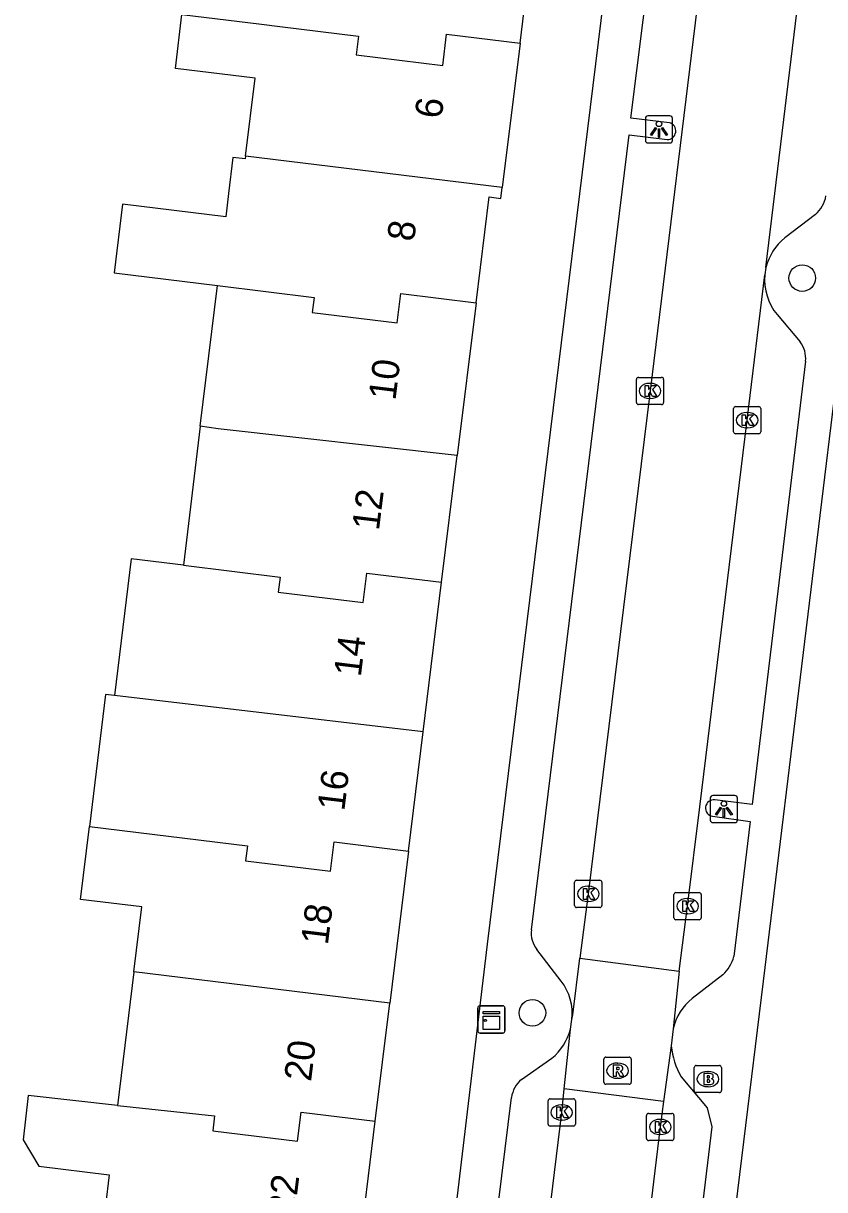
# Model space of a CAD drawing. Extents: x 158087 to 159494, y 382905 to 383981.
# Drawn here: x 158294.96 to 158324.41, y 383327.57 to 383370.44 of the extents above; entities that cross this region are included whole.
import ezdxf

# ---------------------------------------------------------------- set-up
doc = ezdxf.new("R2010")
doc.units = 0
for name, color, linetype in [('IMGEO_Boom', 7, 'Continuous'), ('IMGEO_Brandkraan', 7, 'Continuous'), ('IMGEO_Kast', 7, 'Continuous'), ('IMGEO_Kolk', 7, 'Continuous'), ('IMGEO_Lichtpunt', 7, 'Continuous'), ('IMGEO_Pand', 7, 'Continuous'), ('IMGEO_Pand_nummerreeks', 7, 'Continuous'), ('IMGEO_Rijbaan_lokaal_open', 7, 'Continuous'), ('IMGEO_Rioolput', 7, 'Continuous'), ('IMGEO_Voetpad_open', 7, 'Continuous')]:
    doc.layers.add(name, color=color, linetype=linetype)

msp = doc.modelspace()

# ---------------------------------------------------------------- linework, layer by layer
at = {"layer": 'IMGEO_Boom'}
for centre in [(158323.591, 383361.078), (158313.671, 383334.068)]:
    msp.add_circle(centre, 0.489, dxfattribs=at)
at = {"layer": 'IMGEO_Brandkraan'}
for p, q in [((158319.621, 383331.209), (158319.621, 383332.061)), ((158319.696, 383332.135), (158320.548, 383332.135)), ((158320.109, 383331.915), (158320.134, 383331.915)), ((158320.622, 383332.061), (158320.622, 383331.209)), ((158320.132, 383331.355), (158320.107, 383331.355)), ((158320.548, 383331.135), (158319.696, 383331.135))]:
    msp.add_line(p, q, dxfattribs=at)
for points in [[(158319.621, 383331.209), (158319.621, 383332.061)], [(158319.696, 383332.135), (158320.548, 383332.135)], [(158319.969, 383331.835), (158319.969, 383331.435), (158320.182, 383331.435)], [(158320.2, 383331.835), (158319.969, 383331.835)], [(158320.622, 383332.061), (158320.622, 383331.209)], [(158320.148, 383331.754), (158320.094, 383331.754), (158320.094, 383331.678)], [(158320.094, 383331.678), (158320.147, 383331.678)], [(158320.156, 383331.602), (158320.094, 383331.602), (158320.094, 383331.521)], [(158320.094, 383331.521), (158320.156, 383331.521)], [(158320.548, 383331.135), (158319.696, 383331.135)]]:
    msp.add_lwpolyline(points, dxfattribs=at)
for centre, radius, start, end in [((158319.698, 383332.059), 0.0765, 91.552, 178.448), ((158319.698, 383332.059), 0.0765, 91.552, 178.448), ((158320.204, 383331.69), 0.145, 59.4692, 91.5367), ((158320.229, 383331.737), 0.0922, 285.5137, 58.1501), ((158320.546, 383332.059), 0.0765, 1.552, 88.448), ((158320.546, 383332.059), 0.0765, 1.552, 88.448), ((158320.149, 383331.716), 0.0379, 267.8285, 90.9355), ((158320.157, 383331.561), 0.0404, 269.8759, 90.5077), ((158320.188, 383331.686), 0.251, 268.6676, 293.5347), ((158320.234, 383331.545), 0.105, 301.3115, 78.989), ((158319.698, 383331.211), 0.0765, 181.552, 268.448), ((158319.698, 383331.211), 0.0765, 181.552, 268.448), ((158320.546, 383331.211), 0.0765, 271.552, 358.448), ((158320.546, 383331.211), 0.0765, 271.552, 358.448)]:
    msp.add_arc(centre, radius, start, end, dxfattribs=at)
for centre, major_axis, ratio, start_param, end_param in [((158320.108, 383331.635), (-0.387, 0.002), 0.722429, 4.712389, 7.853982), ((158320.133, 383331.635), (-0.39, 0.002), 0.717154, 1.570796, 4.712389)]:
    msp.add_ellipse(centre, major_axis=major_axis, ratio=ratio, start_param=start_param, end_param=end_param, dxfattribs=at)
at = {"layer": 'IMGEO_Kast'}
for p, q in [((158311.663, 383333.403), (158311.663, 383334.244)), ((158311.663, 383334.244), (158311.663, 383333.403)), ((158311.738, 383334.328), (158312.579, 383334.328)), ((158312.579, 383334.328), (158311.738, 383334.328)), ((158312.663, 383334.253), (158312.663, 383333.412)), ((158312.663, 383333.412), (158312.663, 383334.253)), ((158312.588, 383333.328), (158311.747, 383333.328)), ((158311.747, 383333.328), (158312.588, 383333.328))]:
    msp.add_line(p, q, dxfattribs=at)
for points in [[(158311.858, 383334.118), (158312.458, 383334.118), (158312.458, 383334.033), (158311.858, 383334.033), (158311.858, 383334.118)], [(158311.858, 383333.943), (158312.458, 383333.943), (158312.458, 383333.454), (158311.858, 383333.454), (158311.858, 383333.943)]]:
    msp.add_lwpolyline(points, dxfattribs=at)
msp.add_circle((158311.942, 383333.792), 0.0377, dxfattribs=at)
for centre, start, end in [((158311.741, 383334.25), 92.4484, 184.2845), ((158311.741, 383334.25), 92.4484, 184.2845), ((158312.585, 383334.25), 2.4484, 94.2845), ((158312.585, 383334.25), 2.4484, 94.2845), ((158311.741, 383333.406), 182.4484, 274.2845), ((158311.741, 383333.406), 182.4484, 274.2845), ((158312.585, 383333.406), 272.4484, 4.2845), ((158312.585, 383333.406), 272.4484, 4.2845)]:
    msp.add_arc(centre, 0.0779, start, end, dxfattribs=at)
at = {"layer": 'IMGEO_Kolk'}
for p, q in [((158317.495, 383356.503), (158317.495, 383357.355)), ((158317.57, 383357.429), (158318.422, 383357.429)), ((158317.983, 383357.209), (158318.008, 383357.209)), ((158318.496, 383357.355), (158318.496, 383356.503)), ((158318.006, 383356.649), (158317.981, 383356.649)), ((158318.422, 383356.429), (158317.57, 383356.429)), ((158321.065, 383355.429), (158321.065, 383356.281)), ((158321.14, 383356.355), (158321.992, 383356.355)), ((158322.066, 383356.281), (158322.066, 383355.429)), ((158321.553, 383356.135), (158321.578, 383356.135)), ((158321.576, 383355.575), (158321.551, 383355.575)), ((158321.992, 383355.355), (158321.14, 383355.355)), ((158315.224, 383338.015), (158315.224, 383338.867)), ((158315.299, 383338.941), (158316.151, 383338.941)), ((158315.712, 383338.721), (158315.737, 383338.721)), ((158316.225, 383338.867), (158316.225, 383338.015)), ((158318.875, 383337.564), (158318.875, 383338.416)), ((158318.95, 383338.49), (158319.802, 383338.49)), ((158319.363, 383338.27), (158319.388, 383338.27)), ((158319.876, 383338.416), (158319.876, 383337.564)), ((158316.151, 383337.941), (158315.299, 383337.941)), ((158315.735, 383338.161), (158315.71, 383338.161)), ((158319.802, 383337.49), (158318.95, 383337.49)), ((158319.386, 383337.71), (158319.361, 383337.71)), ((158314.25, 383329.982), (158314.25, 383330.834)), ((158314.325, 383330.908), (158315.177, 383330.908)), ((158314.738, 383330.688), (158314.763, 383330.688)), ((158315.251, 383330.834), (158315.251, 383329.982)), ((158314.761, 383330.128), (158314.736, 383330.128)), ((158317.871, 383329.448), (158317.871, 383330.3)), ((158317.946, 383330.374), (158318.798, 383330.374)), ((158318.359, 383330.154), (158318.384, 383330.154)), ((158318.872, 383330.3), (158318.872, 383329.448)), ((158315.177, 383329.908), (158314.325, 383329.908)), ((158318.798, 383329.374), (158317.946, 383329.374)), ((158318.382, 383329.594), (158318.357, 383329.594))]:
    msp.add_line(p, q, dxfattribs=at)
for points in [[(158317.495, 383356.503), (158317.495, 383357.355)], [(158317.57, 383357.429), (158318.422, 383357.429)], [(158317.816, 383357.129), (158317.939, 383357.129), (158317.939, 383356.978), (158318.069, 383357.129), (158318.233, 383357.129), (158318.087, 383356.978), (158318.24, 383356.729), (158318.088, 383356.729), (158318.003, 383356.893), (158317.939, 383356.826), (158317.939, 383356.729), (158317.816, 383356.729), (158317.816, 383357.129)], [(158318.496, 383357.355), (158318.496, 383356.503)], [(158318.422, 383356.429), (158317.57, 383356.429)], [(158321.065, 383355.429), (158321.065, 383356.281)], [(158321.14, 383356.355), (158321.992, 383356.355)], [(158322.066, 383356.281), (158322.066, 383355.429)], [(158321.386, 383356.055), (158321.509, 383356.055), (158321.509, 383355.904), (158321.639, 383356.055), (158321.803, 383356.055), (158321.657, 383355.904), (158321.81, 383355.655), (158321.658, 383355.655), (158321.573, 383355.819), (158321.509, 383355.752), (158321.509, 383355.655), (158321.386, 383355.655), (158321.386, 383356.055)], [(158321.992, 383355.355), (158321.14, 383355.355)], [(158315.224, 383338.015), (158315.224, 383338.867)], [(158315.299, 383338.941), (158316.151, 383338.941)], [(158315.545, 383338.641), (158315.668, 383338.641), (158315.668, 383338.49), (158315.798, 383338.641), (158315.962, 383338.641), (158315.816, 383338.49), (158315.969, 383338.241), (158315.817, 383338.241), (158315.732, 383338.405), (158315.668, 383338.338), (158315.668, 383338.241), (158315.545, 383338.241), (158315.545, 383338.641)], [(158316.225, 383338.867), (158316.225, 383338.015)], [(158318.875, 383337.564), (158318.875, 383338.416)], [(158318.95, 383338.49), (158319.802, 383338.49)], [(158319.876, 383338.416), (158319.876, 383337.564)], [(158316.151, 383337.941), (158315.299, 383337.941)], [(158319.196, 383338.19), (158319.319, 383338.19), (158319.319, 383338.039), (158319.449, 383338.19), (158319.613, 383338.19), (158319.467, 383338.039), (158319.62, 383337.79), (158319.468, 383337.79), (158319.383, 383337.954), (158319.319, 383337.887), (158319.319, 383337.79), (158319.196, 383337.79), (158319.196, 383338.19)], [(158319.802, 383337.49), (158318.95, 383337.49)], [(158314.25, 383329.982), (158314.25, 383330.834)], [(158314.325, 383330.908), (158315.177, 383330.908)], [(158314.571, 383330.608), (158314.694, 383330.608), (158314.694, 383330.457), (158314.824, 383330.608), (158314.988, 383330.608), (158314.842, 383330.457), (158314.995, 383330.208), (158314.843, 383330.208), (158314.758, 383330.372), (158314.694, 383330.305), (158314.694, 383330.208), (158314.571, 383330.208), (158314.571, 383330.608)], [(158315.251, 383330.834), (158315.251, 383329.982)], [(158317.871, 383329.448), (158317.871, 383330.3)], [(158317.946, 383330.374), (158318.798, 383330.374)], [(158318.192, 383330.074), (158318.315, 383330.074), (158318.315, 383329.923), (158318.445, 383330.074), (158318.609, 383330.074), (158318.463, 383329.923), (158318.616, 383329.674), (158318.464, 383329.674), (158318.379, 383329.838), (158318.315, 383329.771), (158318.315, 383329.674), (158318.192, 383329.674), (158318.192, 383330.074)], [(158318.872, 383330.3), (158318.872, 383329.448)], [(158315.177, 383329.908), (158314.325, 383329.908)], [(158318.798, 383329.374), (158317.946, 383329.374)]]:
    msp.add_lwpolyline(points, dxfattribs=at)
for centre, start, end in [((158317.572, 383357.353), 91.552, 178.448), ((158317.572, 383357.353), 91.552, 178.448), ((158318.42, 383357.353), 1.552, 88.448), ((158318.42, 383357.353), 1.552, 88.448), ((158317.572, 383356.505), 181.552, 268.448), ((158317.572, 383356.505), 181.552, 268.448), ((158318.42, 383356.505), 271.552, 358.448), ((158318.42, 383356.505), 271.552, 358.448), ((158321.142, 383356.279), 91.552, 178.448), ((158321.142, 383356.279), 91.552, 178.448), ((158321.99, 383356.279), 1.552, 88.448), ((158321.99, 383356.279), 1.552, 88.448), ((158321.142, 383355.431), 181.552, 268.448), ((158321.142, 383355.431), 181.552, 268.448), ((158321.99, 383355.431), 271.552, 358.448), ((158321.99, 383355.431), 271.552, 358.448), ((158315.301, 383338.865), 91.552, 178.448), ((158315.301, 383338.865), 91.552, 178.448), ((158316.149, 383338.865), 1.552, 88.448), ((158316.149, 383338.865), 1.552, 88.448), ((158318.952, 383338.414), 91.552, 178.448), ((158318.952, 383338.414), 91.552, 178.448), ((158319.8, 383338.414), 1.552, 88.448), ((158319.8, 383338.414), 1.552, 88.448), ((158315.301, 383338.017), 181.552, 268.448), ((158315.301, 383338.017), 181.552, 268.448), ((158316.149, 383338.017), 271.552, 358.448), ((158316.149, 383338.017), 271.552, 358.448), ((158318.952, 383337.566), 181.552, 268.448), ((158318.952, 383337.566), 181.552, 268.448), ((158319.8, 383337.566), 271.552, 358.448), ((158319.8, 383337.566), 271.552, 358.448), ((158314.327, 383330.832), 91.552, 178.448), ((158314.327, 383330.832), 91.552, 178.448), ((158315.175, 383330.832), 1.552, 88.448), ((158315.175, 383330.832), 1.552, 88.448), ((158317.948, 383330.298), 91.552, 178.448), ((158317.948, 383330.298), 91.552, 178.448), ((158318.796, 383330.298), 1.552, 88.448), ((158318.796, 383330.298), 1.552, 88.448), ((158314.327, 383329.984), 181.552, 268.448), ((158314.327, 383329.984), 181.552, 268.448), ((158315.175, 383329.984), 271.552, 358.448), ((158315.175, 383329.984), 271.552, 358.448), ((158317.948, 383329.45), 181.552, 268.448), ((158317.948, 383329.45), 181.552, 268.448), ((158318.796, 383329.45), 271.552, 358.448), ((158318.796, 383329.45), 271.552, 358.448)]:
    msp.add_arc(centre, 0.0765, start, end, dxfattribs=at)
for centre, major_axis, ratio, start_param, end_param in [((158317.982, 383356.929), (-0.387, 0.002), 0.722429, 4.712389, 7.853982), ((158318.007, 383356.929), (-0.39, 0.002), 0.717154, 1.570796, 4.712389), ((158321.552, 383355.855), (-0.387, 0.002), 0.722429, 4.712389, 7.853982), ((158321.577, 383355.855), (-0.39, 0.002), 0.717154, 1.570796, 4.712389), ((158315.711, 383338.441), (-0.387, 0.002), 0.722429, 4.712389, 7.853982), ((158315.736, 383338.441), (-0.39, 0.002), 0.717154, 1.570796, 4.712389), ((158319.362, 383337.99), (-0.387, 0.002), 0.722429, 4.712389, 7.853982), ((158319.387, 383337.99), (-0.39, 0.002), 0.717154, 1.570796, 4.712389), ((158314.737, 383330.408), (-0.387, 0.002), 0.722429, 4.712389, 7.853982), ((158314.762, 383330.408), (-0.39, 0.002), 0.717154, 1.570796, 4.712389), ((158318.358, 383329.874), (-0.387, 0.002), 0.722429, 4.712389, 7.853982), ((158318.383, 383329.874), (-0.39, 0.002), 0.717154, 1.570796, 4.712389)]:
    msp.add_ellipse(centre, major_axis=major_axis, ratio=ratio, start_param=start_param, end_param=end_param, dxfattribs=at)
at = {"layer": 'IMGEO_Lichtpunt'}
for p, q in [((158317.825, 383366.948), (158317.825, 383366.141)), ((158317.825, 383366.948), (158317.825, 383366.141)), ((158318.727, 383367.043), (158317.919, 383367.043)), ((158318.727, 383367.043), (158317.919, 383367.043)), ((158318.821, 383366.141), (158318.821, 383366.948)), ((158318.821, 383366.141), (158318.821, 383366.948)), ((158317.919, 383366.047), (158318.727, 383366.047)), ((158317.919, 383366.047), (158318.727, 383366.047)), ((158320.211, 383341.963), (158320.211, 383341.156)), ((158320.211, 383341.963), (158320.211, 383341.156)), ((158321.113, 383342.058), (158320.305, 383342.058)), ((158321.113, 383342.058), (158320.305, 383342.058)), ((158321.207, 383341.156), (158321.207, 383341.963)), ((158321.207, 383341.156), (158321.207, 383341.963)), ((158320.305, 383341.062), (158321.113, 383341.062)), ((158320.305, 383341.062), (158321.113, 383341.062))]:
    msp.add_line(p, q, dxfattribs=at)
for points in [[(158318.199, 383366.612), (158318.238, 383366.584), (158318.05, 383366.322), (158318.012, 383366.349), (158318.199, 383366.612)], [(158318.301, 383366.564), (158318.348, 383366.564), (158318.348, 383366.242), (158318.301, 383366.242), (158318.301, 383366.564)], [(158318.411, 383366.584), (158318.449, 383366.611), (158318.636, 383366.349), (158318.597, 383366.321), (158318.411, 383366.584)], [(158320.585, 383341.627), (158320.624, 383341.599), (158320.436, 383341.337), (158320.398, 383341.364), (158320.585, 383341.627)], [(158320.687, 383341.579), (158320.734, 383341.579), (158320.734, 383341.257), (158320.687, 383341.257), (158320.687, 383341.579)], [(158320.797, 383341.599), (158320.835, 383341.626), (158321.022, 383341.364), (158320.983, 383341.336), (158320.797, 383341.599)]]:
    msp.add_lwpolyline(points, dxfattribs=at)
for centre in [(158318.324, 383366.746), (158320.71, 383341.761)]:
    msp.add_circle(centre, 0.0994, dxfattribs=at)
for centre, start, end in [((158317.919, 383366.948), 90, 180), ((158317.919, 383366.948), 90, 180), ((158318.727, 383366.948), 0, 90), ((158318.727, 383366.948), 0, 90), ((158317.919, 383366.141), 180, 270), ((158317.919, 383366.141), 180, 270), ((158318.727, 383366.141), 270, 0), ((158318.727, 383366.141), 270, 360), ((158320.305, 383341.963), 90, 180), ((158320.305, 383341.963), 90, 180), ((158321.113, 383341.963), 0, 90), ((158321.113, 383341.963), 0, 90), ((158320.305, 383341.156), 180, 270), ((158320.305, 383341.156), 180, 270), ((158321.113, 383341.156), 270, 0), ((158321.113, 383341.156), 270, 360)]:
    msp.add_arc(centre, 0.0946, start, end, dxfattribs=at)
at = {"layer": 'IMGEO_Pand'}
for points in [[(158313.218, 383369.715), (158313.778, 383374.266), (158313.353, 383374.416)], [(158303.13, 383365.561), (158303.478, 383368.424), (158300.55, 383368.78), (158300.792, 383370.766)], [(158300.792, 383370.766), (158303.72, 383370.408), (158304.383, 383370.329), (158307.282, 383369.976), (158307.198, 383369.283), (158310.375, 383368.896), (158310.514, 383370.044), (158313.218, 383369.715)], [(158313.218, 383369.715), (158312.566, 383364.413)], [(158303.13, 383365.561), (158303.117, 383365.456), (158302.665, 383365.511), (158302.504, 383364.19), (158302.399, 383363.33), (158298.607, 383363.791), (158298.298, 383361.265), (158302.092, 383360.801)], [(158312.566, 383364.413), (158303.13, 383365.561)], [(158311.6, 383360.171), (158312.079, 383364.061), (158312.516, 383364.007), (158312.566, 383364.413)], [(158301.463, 383355.629), (158302.092, 383360.801)], [(158302.092, 383360.801), (158305.65, 383360.366), (158305.583, 383359.814), (158308.703, 383359.433), (158308.834, 383360.509), (158311.6, 383360.171)], [(158311.6, 383360.171), (158310.909, 383354.558)], [(158301.463, 383355.629), (158300.842, 383350.522)], [(158310.909, 383354.558), (158302.125, 383355.532), (158301.463, 383355.629)], [(158310.335, 383349.894), (158310.909, 383354.558)], [(158300.842, 383350.522), (158298.922, 383350.757), (158298.309, 383345.73)], [(158300.842, 383350.522), (158304.399, 383350.087), (158304.332, 383349.535), (158307.452, 383349.154), (158307.583, 383350.23), (158310.335, 383349.894)], [(158309.659, 383344.401), (158310.335, 383349.894)], [(158298.309, 383345.73), (158297.987, 383345.768), (158297.394, 383340.915)], [(158309.659, 383344.401), (158298.309, 383345.73)], [(158309.119, 383340.015), (158309.659, 383344.401)], [(158299.022, 383335.571), (158299.313, 383337.965), (158297.067, 383338.24), (158297.394, 383340.915)], [(158297.394, 383340.915), (158303.196, 383340.206), (158303.129, 383339.654), (158306.249, 383339.273), (158306.38, 383340.349), (158309.119, 383340.015)], [(158309.119, 383340.015), (158308.43, 383334.426)], [(158299.022, 383335.571), (158298.426, 383330.669)], [(158308.43, 383334.426), (158299.022, 383335.571)], [(158307.897, 383330.09), (158308.43, 383334.426)], [(158298.426, 383330.669), (158295.138, 383331.028), (158294.961, 383329.403), (158295.527, 383328.428), (158298.115, 383328.113), (158297.842, 383325.866)], [(158298.426, 383330.669), (158301.988, 383330.28), (158301.921, 383329.728), (158305.041, 383329.347), (158305.172, 383330.423), (158307.897, 383330.09)], [(158307.266, 383324.969), (158307.897, 383330.09)]]:
    msp.add_lwpolyline(points, dxfattribs=at)
at = {"layer": 'IMGEO_Rijbaan_lokaal_open'}
for points in [[(158322.25, 383361.466), (158323.674, 383373.162), (158324.368, 383379.15)], [(158320.476, 383377.982), (158320.452, 383377.164), (158320.227, 383375.082), (158319.921, 383372.682), (158317.996, 383356.929), (158315.726, 383338.441), (158315.42, 383336.079)], [(158322.25, 383361.466), (158322.217, 383361.195)], [(158319.065, 383335.604), (158319.375, 383337.99), (158319.82, 383341.637), (158321.565, 383355.855), (158322.217, 383361.195)], [(158315.125, 383333.823), (158315.153, 383334), (158315.42, 383336.079)], [(158315.42, 383336.079), (158319.065, 383335.604)], [(158319.065, 383335.604), (158318.844, 383333.487)], [(158315.069, 383333.467), (158315.125, 383333.823)], [(158314.836, 383331.281), (158315.069, 383333.467)], [(158318.844, 383333.487), (158318.775, 383332.853)], [(158318.775, 383332.853), (158318.494, 383330.81)], [(158311.518, 383303.514), (158311.969, 383307.638), (158314.752, 383330.407), (158314.836, 383331.281)], [(158318.494, 383330.81), (158314.836, 383331.281)], [(158318.494, 383330.81), (158318.371, 383329.873), (158316.168, 383311.673), (158315.649, 383307.444), (158315.249, 383304.301)]]:
    msp.add_lwpolyline(points, dxfattribs=at)
at = {"layer": 'IMGEO_Rioolput'}
for p, q in [((158316.301, 383331.517), (158316.301, 383332.369)), ((158316.376, 383332.443), (158317.228, 383332.443)), ((158316.789, 383332.223), (158316.814, 383332.223)), ((158317.302, 383332.369), (158317.302, 383331.517)), ((158317.228, 383331.443), (158316.376, 383331.443)), ((158316.812, 383331.663), (158316.787, 383331.663))]:
    msp.add_line(p, q, dxfattribs=at)
for points in [[(158316.301, 383331.517), (158316.301, 383332.369)], [(158316.376, 383332.443), (158317.228, 383332.443)], [(158317.302, 383332.369), (158317.302, 383331.517)], [(158316.89, 383332.141), (158316.638, 383332.143), (158316.638, 383331.743)], [(158316.638, 383331.743), (158316.762, 383331.743), (158316.762, 383331.905), (158316.773, 383331.905)], [(158316.816, 383332.062), (158316.762, 383332.062), (158316.762, 383331.981)], [(158316.762, 383331.981), (158316.814, 383331.981)], [(158316.82, 383331.876), (158316.891, 383331.743), (158317.031, 383331.743), (158316.966, 383331.869)], [(158317.228, 383331.443), (158316.376, 383331.443)]]:
    msp.add_lwpolyline(points, dxfattribs=at)
for centre, radius, start, end in [((158316.378, 383332.367), 0.0765, 91.552, 178.448), ((158316.378, 383332.367), 0.0765, 91.552, 178.448), ((158317.226, 383332.367), 0.0765, 1.552, 88.448), ((158317.226, 383332.367), 0.0765, 1.552, 88.448), ((158316.772, 383331.852), 0.0533, 26.0293, 88.6989), ((158316.798, 383332.17), 0.19, 274.7715, 282.9687), ((158316.822, 383331.966), 0.0964, 77.0061, 93.1865), ((158316.836, 383332.023), 0.0378, 276.6634, 79.6772), ((158316.889, 383332.031), 0.109, 350.3612, 89.416), ((158316.887, 383332.031), 0.112, 277.5842, 350.9817), ((158316.871, 383331.816), 0.108, 29.5134, 73.7905), ((158316.378, 383331.519), 0.0765, 181.552, 268.448), ((158316.378, 383331.519), 0.0765, 181.552, 268.448), ((158317.226, 383331.519), 0.0765, 271.552, 358.448), ((158317.226, 383331.519), 0.0765, 271.552, 358.448)]:
    msp.add_arc(centre, radius, start, end, dxfattribs=at)
for centre, major_axis, ratio, start_param, end_param in [((158316.788, 383331.943), (-0.387, 0.002), 0.722429, 4.712389, 7.853982), ((158316.813, 383331.943), (-0.39, 0.002), 0.717154, 1.570796, 4.712389)]:
    msp.add_ellipse(centre, major_axis=major_axis, ratio=ratio, start_param=start_param, end_param=end_param, dxfattribs=at)
at = {"layer": 'IMGEO_Voetpad_open'}
for points in [[(158311.12, 383391.319), (158317.588, 383381.778), (158317.256, 383379.22), (158312.006, 383336.596), (158309.154, 383312.647), (158308.137, 383304.132)], [(158318.267, 383303.291), (158319.275, 383311.616), (158322.163, 383335.236), (158325.326, 383361.214), (158327.974, 383383.09)], [(158318.709, 383366.789), (158317.289, 383366.959), (158317.967, 383372.327), (158317.968, 383372.338), (158318.366, 383375.486)], [(158313.636, 383337.122), (158317.228, 383366.345), (158318.624, 383366.167)], [(158324.073, 383363.418), (158322.945, 383362.553)], [(158322.665, 383359.733), (158323.51, 383358.735)], [(158323.713, 383358.02), (158321.749, 383341.723), (158320.375, 383341.898)], [(158320.29, 383341.294), (158321.674, 383341.106), (158321.076, 383336.139)], [(158314.729, 383335.236), (158313.837, 383336.392)], [(158320.672, 383335.468), (158319.546, 383334.594)], [(158313.276, 383331.623), (158314.383, 383332.399)], [(158319.142, 383331.72), (158320.096, 383330.577), (158320.273, 383329.879), (158317.513, 383306.998)], [(158312.032, 383312.454), (158310.647, 383312.686), (158312.903, 383330.955)]]:
    msp.add_lwpolyline(points, dxfattribs=at)
for centre, radius, start, end in [((158318.624, 383366.484), 0.317, 269.98, 74.4568), ((158323.343, 383364.286), 1.134, 310.0634, 350.3011), ((158324.284, 383360.931), 2.103, 129.5415, 165.2709), ((158324.197, 383361.002), 1.989, 174.4359, 219.6374), ((158322.742, 383358.131), 0.977, 353.4993, 38.2008), ((158320.34, 383341.595), 0.305, 83.4421, 260.5369), ((158314.631, 383337.003), 1.002, 173.2036, 217.5854), ((158319.721, 383336.498), 1.402, 312.7235, 345.1734), ((158313.174, 383334.038), 1.963, 353.703, 37.6085), ((158320.758, 383333.049), 1.963, 128.1179, 167.1208), ((158313.109, 383333.972), 2.024, 309.0116, 345.5614), ((158321.542, 383333.123), 2.78, 185.5811, 210.3151), ((158313.939, 383330.815), 1.045, 129.357, 172.2865)]:
    msp.add_arc(centre, radius, start, end, dxfattribs=at)

# ---------------------------------------------------------------- texts
at = {"layer": 'IMGEO_Pand_nummerreeks'}
for s, rotation, p in [('6', 82.9871, (158310.334, 383366.911)), ('8', 82.9815, (158309.32, 383362.397)), ('10', 82.9812, (158308.637, 383356.556)), ('12', 82.9815, (158308.03, 383351.772)), ('14', 82.9815, (158307.363, 383346.392)), ('16', 82.9815, (158306.757, 383341.464)), ('18', 82.9812, (158306.152, 383336.538)), ('20', 82.9812, (158305.534, 383331.521)), ('22', 82.9815, (158304.925, 383326.588))]:
    msp.add_text(s, height=1, rotation=rotation, dxfattribs=at).set_placement(p)

doc.saveas('drawing.dxf')
